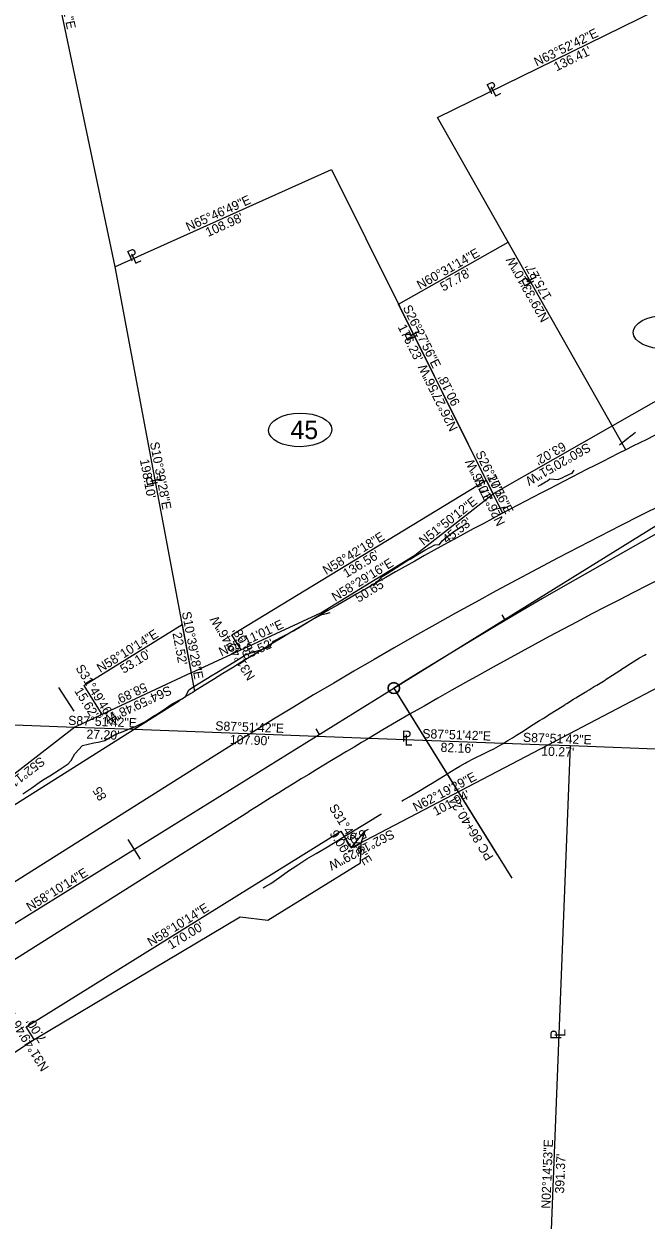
# Model space of a CAD drawing. Extents: x 1145508 to 2262867, y -3126236 to 2021677.
# Drawn here: x 1151042 to 1151328, y 2019963 to 2020512 of the extents above; entities that cross this region are included whole.
import ezdxf

# ---------------------------------------------------------------- set-up
doc = ezdxf.new("R2010")
doc.units = 0
for name, color, linetype in [('Default', 7, 'Continuous'), ('DSN_DRFT_Guideline-No-Plot', 7, 'Continuous'), ('DSN_RDWY_Alignment', 7, 'Continuous'), ('DSN_RDWY_Alignment Annotation', 7, 'Continuous'), ('DSN_RDWY_Const Limits', 7, 'Continuous'), ('DSN_ROW_Annotation', 7, 'Continuous'), ('DSN_ROW_Esmnt', 7, 'Continuous'), ('DSN_ROW_Line', 7, 'Continuous'), ('DSN_ROW_Line-Annotation', 7, 'Continuous'), ('DSN_ROW_Prop-Line', 7, 'Continuous'), ('DSN_ROW_Prop-Line-Annotation', 7, 'Continuous'), ('E_Const Align', 7, 'Continuous'), ('EX_QSECTION', 7, 'Continuous'), ('EX_ROW', 7, 'Continuous'), ('EX_ROW_ANNOT', 7, 'Continuous'), ('EX_SIGN', 7, 'Continuous'), ('SHET_Annotations', 7, 'Continuous')]:
    doc.layers.add(name, color=color, linetype=linetype)

msp = doc.modelspace()

# ---------------------------------------------------------------- linework, layer by layer
at = {"layer": 'Default'}
msp.add_line((1151129.4, 2020175.6), (1150710.33, 2019911.3), dxfattribs=at)
msp.add_arc((1152351.97, 2018237.09), 2291.83, 105.0994, 122.23857, dxfattribs=at)
at = {"layer": 'DSN_DRFT_Guideline-No-Plot'}
for p, q in [((1151196.6, 2020126.7), (1151196.6, 2020126.7)), ((1151154.12, 2020100.33), (1151154.12, 2020100.33))]:
    msp.add_line(p, q, dxfattribs=at)
at = {"layer": 'DSN_RDWY_Alignment'}
msp.add_line((1151211.88, 2020206.81), (1151574.96, 2020432.19), dxfattribs=at)
msp.add_lwpolyline([(1151211.88, 2020206.81), (1151265.98, 2020119.67)], dxfattribs=at)
msp.add_circle((1151211.88, 2020206.81), 2.5, dxfattribs=at)
at = {"layer": 'DSN_RDWY_Alignment Annotation'}
for p, q in [((1151261.46, 2020240.38), (1151262.98, 2020237.8)), ((1151211.88, 2020206.81), (1151211.88, 2020206.81)), ((1151213.29, 2020204.54), (1151259.35, 2020130.35)), ((1151176.12, 2020188.14), (1151177.7, 2020185.59)), ((1151089.92, 2020137.39), (1151095.52, 2020128.37)), ((1151259.35, 2020130.35), (1151259.35, 2020130.35))]:
    msp.add_line(p, q, dxfattribs=at)
msp.add_circle((1151211.88, 2020206.81), 2.67, dxfattribs=at)
at = {"layer": 'DSN_RDWY_Const Limits'}
for points in [[(1151315.48, 2020318.49), (1151319.33, 2020321.6), (1151319.5, 2020321.73), (1151319.97, 2020322.12), (1151321.15, 2020323.1), (1151322.78, 2020324.25)], [(1151278.12, 2020299.47), (1151279.2, 2020300.14), (1151281.5, 2020301.5), (1151282.35, 2020302), (1151283.51, 2020302.84), (1151287.06, 2020302.51), (1151289.05, 2020303.36), (1151290.76, 2020304.19), (1151290.88, 2020304.25), (1151292.12, 2020304.88), (1151293.57, 2020305.45), (1151293.67, 2020305.51), (1151294.68, 2020306.82)], [(1151258.11, 2020288.88), (1151261.78, 2020289.68), (1151262.98, 2020289.94)], [(1151202.59, 2020253.75), (1151204.85, 2020256.21), (1151206.03, 2020257.63), (1151206.58, 2020257.97), (1151208.83, 2020259.44), (1151213.09, 2020262.22), (1151215.19, 2020263.58), (1151217.36, 2020264.98), (1151219.36, 2020266.03), (1151221.8, 2020267.46), (1151224.58, 2020269.13), (1151226.16, 2020270.06), (1151230.62, 2020272.51), (1151232.85, 2020272.68), (1151234.11, 2020274.46), (1151234.97, 2020275.14), (1151238.98, 2020278.34), (1151242.3, 2020280.49), (1151242.64, 2020280.69), (1151242.98, 2020280.9), (1151243.27, 2020281.07), (1151245.31, 2020282.35)], [(1151041.66, 2020158.25), (1151045.83, 2020161), (1151049.86, 2020164), (1151051.48, 2020164.99), (1151054.12, 2020166.62), (1151058.28, 2020169.4), (1151062.49, 2020172.09), (1151063.85, 2020173.54), (1151065.55, 2020176.64), (1151069.09, 2020180.43), (1151074.2, 2020181.67), (1151076.24, 2020182.01), (1151079.37, 2020182.82), (1151083.7, 2020185.32), (1151088.42, 2020187.2), (1151090.22, 2020187.94), (1151093.11, 2020189.13), (1151097.66, 2020191.28), (1151101.84, 2020194.03), (1151102.67, 2020194.58), (1151103.43, 2020195.08), (1151106.01, 2020196.78), (1151110.19, 2020199.54), (1151114.56, 2020201.98), (1151116.25, 2020202.89), (1151117.91, 2020206.06), (1151122.13, 2020208.74), (1151126.33, 2020211.46), (1151128.12, 2020212.53), (1151130.63, 2020214.02), (1151134.91, 2020216.6), (1151139.17, 2020219.22), (1151140.93, 2020220.32), (1151143.4, 2020221.86), (1151143.41, 2020221.87), (1151148.21, 2020223.62), (1151153.15, 2020225.14), (1151155.15, 2020225.85), (1151156.65, 2020228.43), (1151156.91, 2020228.57), (1151161.39, 2020230.82), (1151165.89, 2020233.06), (1151167.58, 2020234.13), (1151167.68, 2020234.2), (1151170.12, 2020235.72), (1151174.4, 2020238.31), (1151178.86, 2020240.6), (1151181.04, 2020241.09), (1151182.69, 2020241.59)], [(1151215.58, 2020155.02), (1151216.39, 2020155.49), (1151216.49, 2020155.55), (1151218.99, 2020156.99), (1151223.33, 2020159.48), (1151227.59, 2020162.09), (1151229.4, 2020163.2), (1151231.86, 2020164.71), (1151236.12, 2020167.32), (1151236.32, 2020167.45), (1151240.33, 2020169.88), (1151242.12, 2020170.94), (1151244.56, 2020172.39), (1151245.38, 2020172.88), (1151248.88, 2020174.75), (1151253.35, 2020176.86), (1151254.89, 2020177.58), (1151255.47, 2020177.84), (1151257.79, 2020179.03), (1151262.05, 2020181.48), (1151264.12, 2020182.73), (1151266.25, 2020184.03), (1151268.1, 2020185.2), (1151270.41, 2020186.66), (1151273.07, 2020188.34), (1151274.56, 2020189.3), (1151278.73, 2020191.91), (1151280.38, 2020192.95), (1151282.01, 2020193.97), (1151282.89, 2020194.53), (1151287.06, 2020197.15), (1151290.3, 2020199.18), (1151290.61, 2020199.4), (1151290.94, 2020199.62), (1151291.21, 2020199.79), (1151294.37, 2020201.73), (1151295.4, 2020202.37), (1151296.65, 2020203.13), (1151299.6, 2020204.93), (1151299.94, 2020205.14), (1151299.95, 2020205.15), (1151300.49, 2020205.48), (1151301.43, 2020206.05), (1151303.8, 2020207.49), (1151305.05, 2020208.25), (1151307.99, 2020210.06), (1151308.94, 2020210.68), (1151309.3, 2020210.91), (1151312.13, 2020212.73), (1151315.49, 2020214.89), (1151316.27, 2020215.39), (1151316.35, 2020215.44), (1151317.84, 2020216.4), (1151320.42, 2020218.05), (1151324.6, 2020220.65), (1151326.84, 2020221.95), (1151327.66, 2020222.42)], [(1151151.92, 2020115.24), (1151152.71, 2020115.7), (1151155.41, 2020117.22), (1151159.51, 2020120.09), (1151163.61, 2020122.96), (1151165.2, 2020124.02), (1151167.77, 2020125.74), (1151171.98, 2020128.43), (1151176.3, 2020130.95), (1151178.1, 2020132.01), (1151180.62, 2020133.49), (1151184.9, 2020136.07), (1151189.15, 2020138.7), (1151190.92, 2020139.78), (1151193.4, 2020141.32), (1151193.41, 2020141.32), (1151197.68, 2020143.91), (1151201.93, 2020146.56), (1151203.69, 2020147.65), (1151205.92, 2020149.04), (1151206.17, 2020149.2)]]:
    msp.add_lwpolyline(points, dxfattribs=at)
at = {"layer": 'DSN_ROW_Esmnt'}
for p, q in [((1151214.06, 2020382.96), (1151264.36, 2020411.4)), ((1151254.25, 2020302.23), (1151214.06, 2020382.96)), ((1151137.56, 2020231.3), (1151254.25, 2020302.23)), ((1151254.25, 2020302.23), (1151257.38, 2020295.95)), ((1151257.38, 2020295.95), (1151254.25, 2020302.23)), ((1151069.65, 2020207.97), (1151114.76, 2020235.98)), ((1151114.76, 2020235.98), (1151118.93, 2020213.85)), ((1151141.82, 2020224.43), (1151137.56, 2020231.3)), ((1151069.65, 2020207.97), (1151077.88, 2020194.7)), ((1151196.82, 2020135.83), (1151192.38, 2020133.5))]:
    msp.add_line(p, q, dxfattribs=at)
at = {"layer": 'DSN_ROW_Line'}
for p, q in [((1151413.84, 2020385.02), (1151312.14, 2020327.13)), ((1151312.14, 2020327.13), (1151257.38, 2020295.95)), ((1151282.65, 2020180.85), (1151544.76, 2020318.25)), ((1151221.58, 2020267.82), (1151257.38, 2020295.95)), ((1151178.4, 2020241.35), (1151221.58, 2020267.82)), ((1151118.93, 2020213.85), (1151178.4, 2020241.35)), ((1151118.93, 2020213.85), (1151065.55, 2020188.95)), ((1151065.55, 2020188.95), (1151004.78, 2020141.81)), ((1151192.38, 2020133.5), (1151282.65, 2020180.85)), ((1151043.2, 2020051.49), (1151187.63, 2020141.15)), ((1151187.63, 2020141.15), (1151192.38, 2020133.5)), ((1151046.89, 2020045.54), (1151043.2, 2020051.49)), ((1150933.54, 2019971.66), (1151046.89, 2020045.54))]:
    msp.add_line(p, q, dxfattribs=at)
at = {"layer": 'DSN_ROW_Line-Annotation'}
for centre in [(1151336.24, 2020370.16), (1151168.9, 2020325.28)]:
    msp.add_ellipse(centre, major_axis=(14.54, 0.23), ratio=0.529773, dxfattribs=at)
at = {"layer": 'DSN_ROW_Prop-Line'}
for p, q in [((1151032.27, 2020646.17), (1151083.87, 2020400.12)), ((1151231.91, 2020468.63), (1151354.39, 2020528.69)), ((1151318.36, 2020316.16), (1151231.91, 2020468.63)), ((1151083.87, 2020400.12), (1151183.26, 2020444.83)), ((1151183.26, 2020444.83), (1151261.8, 2020287.07)), ((1151083.87, 2020400.12), (1151120.51, 2020205.44)), ((1151277.57, 2019789.4), (1151292.92, 2020180.46))]:
    msp.add_line(p, q, dxfattribs=at)
at = {"layer": 'E_Const Align'}
for p, q in [((1150907.91, 2020018.13), (1151211.88, 2020206.81)), ((1151196.6, 2020126.7), (1151196.82, 2020135.83)), ((1151196.6, 2020126.7), (1151196.82, 2020135.83)), ((1151154.12, 2020100.33), (1151196.6, 2020126.7)), ((1151154.12, 2020100.33), (1151196.6, 2020126.7)), ((1151046.89, 2020045.54), (1151141.4, 2020101.86)), ((1151046.89, 2020045.54), (1151141.4, 2020101.86)), ((1151141.4, 2020101.86), (1151154.12, 2020100.33)), ((1151141.4, 2020101.86), (1151154.12, 2020100.33))]:
    msp.add_line(p, q, dxfattribs=at)
msp.add_arc((1152722.75, 2017772.83), 2864.79, 104.86102, 121.82944, dxfattribs=at)
msp.add_arc((1152722.75, 2017772.83), 2864.79, 104.86102, 121.82944, dxfattribs=at)
at = {"layer": 'EX_QSECTION'}
for p, q in [((1150915.35, 2020194.56), (1151065.55, 2020188.95)), ((1151065.55, 2020188.95), (1151092.73, 2020187.94)), ((1151092.73, 2020187.94), (1151200.55, 2020183.91)), ((1151200.55, 2020183.91), (1151282.65, 2020180.85)), ((1151282.65, 2020180.85), (1151292.92, 2020180.46)), ((1151292.92, 2020180.46), (1151612.73, 2020168.52))]:
    msp.add_line(p, q, dxfattribs=at)
at = {"layer": 'EX_ROW'}
for p, q in [((1151092.73, 2020187.94), (1151113.4, 2020200.97)), ((1150824.51, 2020018.78), (1151092.73, 2020187.94)), ((1150925.13, 2020011.3), (1151145.4, 2020150.22))]:
    msp.add_line(p, q, dxfattribs=at)
for radius, start, end in [(2321.83, 113.60439, 116.43421), (2321.83, 116.43421, 118.00384), (2261.83, 114.69172, 120.60151), (2321.83, 118.00384, 122.03134), (2321.83, 122.03134, 122.23857), (2261.83, 120.60151, 122.23857)]:
    msp.add_arc((1152351.97, 2018237.09), radius, start, end, dxfattribs=at)
at = {"layer": 'EX_SIGN'}
msp.add_line((1151058.11, 2020207.03), (1151065.08, 2020196.27), dxfattribs=at)
at = {"layer": 'SHET_Annotations'}
msp.add_line((1151192.38, 2020133.5), (1151198.79, 2020141.27), dxfattribs=at)
msp.add_lwpolyline([(1151196.82, 2020135.83), (1151198.79, 2020141.27), (1151200.31, 2020142.05)], dxfattribs=at)

# ---------------------------------------------------------------- texts
at = {"layer": 'DSN_RDWY_Alignment Annotation'}
for s, rotation, p in [('85', 121.8294, (1151080.34, 2020156.8)), ('86+40.24', 121.8294, (1151252.81, 2020137.48)), ('PC', 121.8294, (1151257.82, 2020129.4)), ('N58°10\'14"E', 31.8294, (1151044.93, 2020104.24))]:
    msp.add_text(s, height=4.2, rotation=rotation, dxfattribs=at).set_placement(p)
at = {"layer": 'DSN_ROW_Annotation'}
for s, rotation, p in [('S11°50\'41"E', 281.8448, (1151055.51, 2020539.74)), ('N63°52\'42"E', 26.1215, (1151277.44, 2020491.96)), ("136.41'", 26.1215, (1151286.54, 2020489.74)), ('N65°46\'49"E', 24.2198, (1151117.64, 2020416.3)), ("108.98'", 24.2198, (1151126.67, 2020413.78)), ('N60°31\'14"E', 29.4794, (1151223.92, 2020389.57)), ('N29°33\'10"W', 119.5529, (1151283.26, 2020376.24)), ("57.78'", 29.4794, (1151234.63, 2020388.73)), ("175.27'", 119.5529, (1151284.43, 2020386.34)), ('S26°27\'56"E', 296.4657, (1151215.86, 2020381.36)), ("176.23'", 296.4657, (1151213.57, 2020372.5)), ('N26°27\'56"W', 116.4657, (1151241.4, 2020326.02)), ("90.18'", 116.4657, (1151242.35, 2020337.57)), ('S10°39\'28"E', 280.6579, (1151099.97, 2020319.42)), ('S60°20\'51"W', 209.6526, (1151300.65, 2020319.55)), ("63.02'", 209.6526, (1151289.32, 2020320.01)), ("198.10'", 280.6579, (1151095.35, 2020311.53)), ('N26°27\'56"W', 116.4657, (1151263.06, 2020282.52)), ('S26°27\'56"E', 296.4657, (1151249.15, 2020314.5)), ("7.01'", 296.4657, (1151248.37, 2020302.59)), ("7.01'", 116.4657, (1151263.25, 2020295.59)), ('N51°50\'12"E', 38.1635, (1151225.51, 2020272.05)), ("45.53'", 38.1635, (1151236.22, 2020272.84)), ('N58°42\'18"E', 31.2949, (1151180.86, 2020258.67)), ("136.56'", 31.2949, (1151190.13, 2020257.28)), ('N58°29\'16"E', 31.5122, (1151184.98, 2020246.44)), ("50.65'", 31.5122, (1151195.71, 2020245.97)), ('S10°39\'28"E', 280.6579, (1151114.63, 2020241.55)), ('N31°49\'46"W', 121.8294, (1151148.45, 2020212.04)), ('N58°10\'14"E', 31.8294, (1151077.24, 2020213.74)), ('N65°11\'01"E', 24.8163, (1151132.8, 2020221.25)), ("8.08'", 121.8294, (1151147.42, 2020225.08)), ("22.52'", 280.6579, (1151110.33, 2020231.98)), ("65.52'", 24.8163, (1151143.4, 2020219.55)), ("53.10'", 31.8294, (1151087.97, 2020213.34)), ('S31°49\'46"E', 301.8294, (1151065.69, 2020216.05)), ("15.62'", 301.8294, (1151065.13, 2020205.57)), ('S64°59\'48"W', 205.0034, (1151108.72, 2020208.09)), ("58.89'", 205.0034, (1151097.47, 2020209.47)), ('S52°11\'59"W', 217.8001, (1151049.76, 2020175.57)), ('N62°19\'29"E', 27.6753, (1151221.99, 2020150.05)), ("101.94'", 27.6753, (1151231.15, 2020148.08)), ('S31°49\'46"E', 301.8294, (1151181.93, 2020152.04)), ('S62°19\'29"W', 207.6753, (1151210.75, 2020142.12)), ("9.00'", 301.8294, (1151182.27, 2020140.11)), ("5.01'", 207.6753, (1151197.94, 2020142.18)), ('N58°10\'14"E', 31.8294, (1151100.45, 2020088.09)), ("170.00'", 31.8294, (1151109.73, 2020086.79)), ('N31°49\'46"W', 121.8294, (1151053.8, 2020032.69)), ("7.00'", 121.8294, (1151052.77, 2020045.73)), ('N02°14\'53"E', 87.752, (1151283.67, 2019967.92)), ("391.37'", 87.752, (1151289.95, 2019974.88))]:
    msp.add_text(s, height=4.2, rotation=rotation, dxfattribs=at).set_placement(p)
at = {"layer": 'DSN_ROW_Esmnt'}
msp.add_text('b', height=2, dxfattribs=at).set_placement((1151076.88, 2020193.7))
at = {"layer": 'DSN_ROW_Line-Annotation'}
msp.add_text('45', height=8.5, dxfattribs=at).set_placement((1151164.5, 2020321.07))
at = {"layer": 'DSN_ROW_Prop-Line-Annotation'}
for s, rotation, p in [('P', 26.7392, (1151256.08, 2020479.07)), ('L', 26.7392, (1151257.98, 2020477.88)), ('P', 24.7255, (1151091.05, 2020402.45)), ('L', 24.7255, (1151092.92, 2020401.19)), ('P', 116.9943, (1151276.53, 2020392.84)), ('L', 116.9943, (1151277.71, 2020394.75)), ('L', 116.9943, (1151224.01, 2020369.8)), ('P', 116.9943, (1151222.83, 2020367.89)), ('L', 102.1946, (1151105.3, 2020301.91)), ('P', 102.1946, (1151103.67, 2020300.37)), ('P', 90, (1151288.69, 2020045.65)), ('L', 90, (1151290.6, 2020046.82))]:
    msp.add_text(s, height=5, rotation=rotation, dxfattribs=at).set_placement(p)
for s, p in [('P', (1151215.53, 2020182.32)), ('L', (1151216.69, 2020180.4))]:
    msp.add_text(s, height=5, dxfattribs=at).set_placement(p)
at = {"layer": 'EX_ROW_ANNOT'}
for s, p in [('S87°51\'42"E', (1151062.42, 2020189.97)), ('S87°51\'42"E', (1151062.42, 2020189.97)), ('S87°51\'42"E', (1151129.92, 2020187.45)), ('S87°51\'42"E', (1151129.92, 2020187.45)), ("27.20'", (1151070.8, 2020183.65)), ("27.20'", (1151070.8, 2020183.65)), ("107.90'", (1151136.6, 2020181.2)), ("107.90'", (1151136.6, 2020181.2)), ('S87°51\'42"E', (1151224.88, 2020183.9)), ('S87°51\'42"E', (1151224.88, 2020183.9)), ('S87°51\'42"E', (1151271.07, 2020182.18)), ('S87°51\'42"E', (1151271.07, 2020182.18)), ("82.16'", (1151233.26, 2020177.59)), ("82.16'", (1151233.26, 2020177.59)), ("10.27'", (1151279.45, 2020175.86)), ("10.27'", (1151279.45, 2020175.86))]:
    msp.add_text(s, height=4.2, rotation=357.8615, dxfattribs=at).set_placement(p)

doc.saveas('drawing.dxf')
